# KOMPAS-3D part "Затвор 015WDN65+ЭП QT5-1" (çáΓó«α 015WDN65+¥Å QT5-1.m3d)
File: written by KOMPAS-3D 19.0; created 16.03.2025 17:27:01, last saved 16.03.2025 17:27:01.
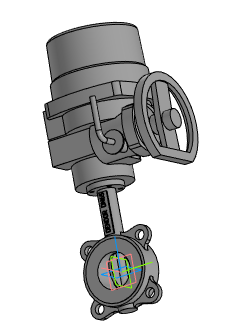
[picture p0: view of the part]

Document properties: Полное имя файла: Затвор 015WDN65+ЭП QT5-1.a3d

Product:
- Part/product: Затвор 015WDN65+ЭП QT5-1
    Масса: 44.2155

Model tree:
1. Операция без истории:1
